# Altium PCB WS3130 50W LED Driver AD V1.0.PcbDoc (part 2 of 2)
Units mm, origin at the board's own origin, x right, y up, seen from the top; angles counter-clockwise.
Board outline 122.48 x 39.96 mm, 2 copper layers (Top Layer, Bottom Layer); 58 components, 32 nets, 164 pads, 32 vias.
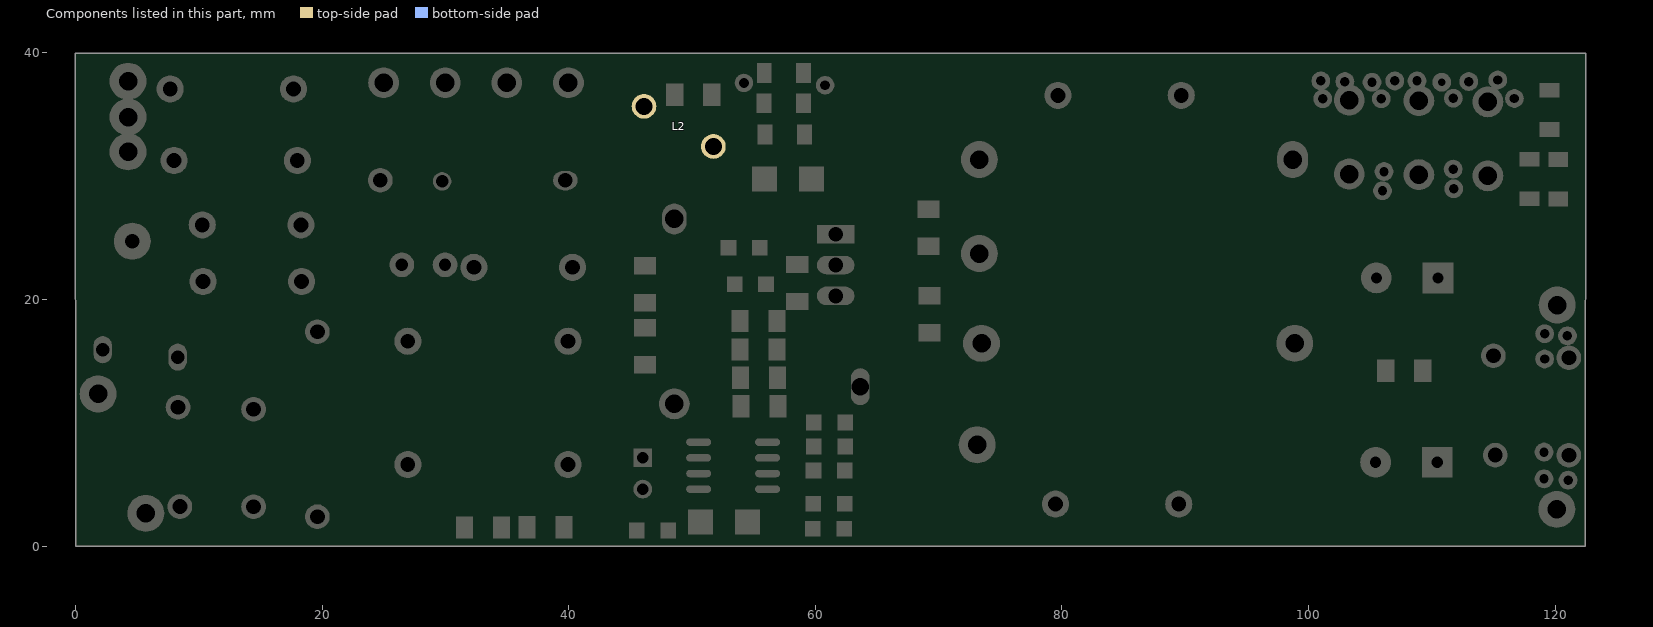
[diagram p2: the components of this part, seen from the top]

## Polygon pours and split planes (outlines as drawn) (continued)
VBUS on Bottom Layer "Bottom Layer-VBUS 1" (hatched 90Degree grid 0.3 track 0.305, remove dead copper, pour order 1065): 219.059,-19.774
G on Bottom Layer "Bottom Layer-G" (hatched 90Degree grid 0.2 track 0.203, remove dead copper, pour order 1064): 199.309,-18.024
GNDE on Bottom Layer "Bottom Layer-GNDE 1" (hatched 90Degree grid 0.051 track 0.051, pour order 1063): -216.941,-285.774
L2 on Bottom Layer "Bottom Layer-L2 1" (hatched Vertical grid 0.1 track 0.203, pour order 1056): 36.239,39.481
TS on Bottom Layer "Bottom Layer-TS" (hatched Vertical grid 0.1 track 0.203, pour order 1048): 97.02,30.025 99.43,30.025 99.865,30.46 99.865,33.321 100.768,34.225 96.69,34.225 96.69,30.025
LED+ on Bottom Layer "Top Layer-No Net" (solid, remove dead copper, pour order 1006): 119.803,21.469 118.772,21.469 ccw(c118.772,20.75) 118.053,20.75 118.053,13.975 ccw(c118.953,13.975) 118.953,13.075 121.228,13.075 ccw(c121.228,13.975) 122.128,13.975 122.128,20.194 ccw(c120.853,20.194) 120.853,21.469 119.503,21.469
LED- on Bottom Layer "Top Layer-No Net" (solid, remove dead copper, pour order 1007): 120.078,9.245 118.923,9.245 ccw(c118.923,8.3) 117.978,8.3 117.978,1.75 ccw(c118.853,1.75) 118.853,0.875 121.191,0.875 ccw(c121.191,1.837) 122.153,1.837 122.153,3.6 122.153,8.62 ccw(c121.528,8.62) 121.528,9.245 120.078,9.245
gnd1 on Bottom Layer "Top Layer-gnd1" (solid, remove dead copper, pour order 1027): 5.103,39.387 3.863,39.387 ccw(c3.863,37.5) 1.976,37.5 1.976,31.9 ccw(c3.576,31.9) 3.576,30.3 8.578,30.3 ccw(c8.578,31.4) 9.678,31.4 9.678,37.762 ccw(c8.053,37.762) 8.053,39.387 5.176,39.387
GND2 on Bottom Layer "Top Layer-GND2" (solid, remove dead copper, pour order 1028): 10.378,27.225 9.003,27.225 ccw(c9.003,26.561) 8.534,27.031 8.328,26.825 cw(c7.483,27.67) 7.483,26.475 6.853,26.475 3.603,26.475 ccw(c3.603,25.45) 2.578,25.45 2.578,23.825 ccw(c3.403,23.825) 3.403,23 7.131,23 cw(c7.131,21.378) 8.278,22.525 cw(c7.554,21.801) 8.578,21.801 8.578,21.325 ccw(c9.604,21.325) 9.604,20.299 9.953,20.299 10.957,20.299 ccw(c10.957,21.2) 11.859,21.2 11.859,26.194 ccw(c10.828,26.194) 10.828,27.225 10.378,27.225
L on Bottom Layer "Top Layer-L" (solid, remove dead copper, pour order 1029): 2.303,17.25 1.103,17.25 ccw(c1.103,16.525) 0.378,16.525 0.378,11.575 ccw(c1.203,11.575) 1.203,10.75 2.603,10.75 ccw(c2.603,11.575) 3.428,11.575 3.428,16.65 ccw(c2.828,16.65) 2.828,17.25 2.303,17.25
L0 on Bottom Layer "Top Layer-L0" (solid, remove dead copper, pour order 1030): 8.703,16.5 8.003,16.5 ccw(c8.003,15.7) 7.203,15.7 7.203,11 ccw(c8.153,11) 8.153,10.05 9.259,10.05 ccw(c9.259,10.95) 10.159,10.95 10.159,15.644 ccw(c9.303,15.644) 9.303,16.5 8.703,16.5
N0 on Bottom Layer "Top Layer-N0" (solid, remove dead copper, pour order 1031): 5.678,4.5 5.221,4.5 ccw(c5.221,3.457) 4.178,3.457 4.178,1.925 ccw(c5.278,1.925) 5.278,0.825 8.903,0.825 ccw(c8.903,1.675) 9.753,1.675 9.753,3.45 ccw(c8.703,3.45) 8.703,4.5 5.678,4.5

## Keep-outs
Keep-Out Layer:
  lines w0.254: -0.011,0.094 -0.011,39.954 ; 0,0 122.439,0 ; 0,39.96 122.472,39.96 122.461,-0.02 ; 0.04,-2.057 0.04,-1.549 ; 1.564,-2.312 0.04,-1.803 ; 1.564,-1.296 0.04,-1.803 ; 51.241,-1.817 0.04,-1.803 ; 71.352,-1.822 122.553,-1.835 ; 121.029,-2.342 122.553,-1.835 ; 121.029,-1.326 122.553,-1.835 ; 122.553,-2.089 122.553,-1.581 ; 123.745,38.245 124.243,39.772 ; 123.976,1.293 124.493,-0.228 ; 123.989,39.771 124.497,39.774 ; 124.239,-0.229 124.747,-0.226 ; 124.309,29.32 124.243,39.772 ; 124.428,10.225 124.493,-0.228 ; 124.761,38.251 124.243,39.772 ; 124.992,1.299 124.493,-0.228
  lines w0.5: 57.028,22.15 57.603,21.575 63.703,21.575 ; 57.178,24.025 63.678,24.025
  lines w1: 18.469,33.508 20.95,31.026
  lines w1.016: 2.836,5.34 7.626,5.34 ; 8.114,18.85 12.359,18.85 ; 16.504,23.741 19.961,23.741 21.552,22.149 21.552,13.773 25.525,9.8 29.756,9.8 ; 20.549,6.028 22.599,3.977 29.369,3.977 ; 20.95,31.026 20.95,28.703 24.45,25.204 24.45,15.967 26.07,14.347 28.351,14.347 ; 84.098,0.357 84.098,5.75 ; 84.098,5.627 84.098,7.778 ; 84.672,28.947 84.672,39.589
  lines w2: 5.446,10.015 5.446,17.359
  text "40.00078 (mm)" at 123.396,29.06 h1.52 r270.36
  text "122.51282 (mm)" at 51.495,-2.731 h1.52 r359.99

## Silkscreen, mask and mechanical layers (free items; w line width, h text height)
Top Overlay:
  lines w0.15: 43.503,15.2 44.203,15.2 44.228,15.175 ; 43.653,15.725 43.653,20.125 ; 43.653,15.825 43.653,15.75 44.228,15.175 ; 56.053,22.85 56.053,22.475 ; 56.803,27.725 56.803,23.225 56.053,22.475 ; 64.351,0.075 69.297,0.075 ; 64.351,39.8 69.278,39.8 69.278,35.594 ; 44.228,15.175 44.228,15.875 44.228,15.175 ; 56.053,22.475 56.478,22.475 ; 56.478,22.475 56.478,22.475
  lines w0.152: 64.351,0.075 64.351,39.8 ; 69.278,35.95 69.297,35.932 69.297,0.075
  text "Street" at 69.75,37.975 h1
  text "Light" at 70.8,36.05 h1
  text "Driver" at 72.175,34.05 h1
  text "GND" at 2.328,33.2 h1 r90
  text "GND2" at 0.853,29.025 h1
  text "LED+" at 115.378,22.3 h1.5
  text "+" at 116.948,12.169 h1.52
  text "L" at 1.303,8.525 h1.52
  text "Winsemi" at 92.903,4.275 h1.2
  text "WS3130" at 92.578,2.125 h1
  text "V1.0" at 98.875,2 h1
  text "N" at 1.053,1.625 h1.52
  text "LED-" at 114.028,0.6 h1.5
